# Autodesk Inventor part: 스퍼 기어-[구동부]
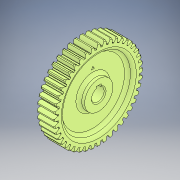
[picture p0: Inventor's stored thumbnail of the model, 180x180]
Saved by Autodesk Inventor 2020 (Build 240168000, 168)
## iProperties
Created: 2025-02
Part Number: 스퍼 기어-[구동부]
Material: 강철, 탄소
Document SubType Name: Modeling
Designer: 1강의실14
Density: 7.85 g/cm^3
Appearance: 반연마
Mass: 521.438 g
Surface Area: 247.111 cm^2
Volume: 66.4252 cm^3
Sending System: Autodesk Inventor 2025
Preprocessor: ST-DEVELOPER v20
Author: jhkim
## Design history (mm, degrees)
feature "솔리드1"
node "솔리드2"
